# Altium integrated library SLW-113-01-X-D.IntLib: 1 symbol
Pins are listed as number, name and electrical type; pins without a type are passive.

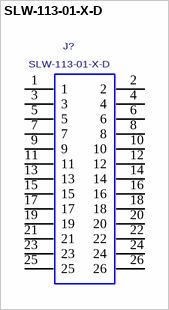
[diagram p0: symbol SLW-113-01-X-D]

## SLW-113-01-X-D
designator J?
LOW PROFILE, DOUBLE ROW, 0.100"SOCKET STRIP ASSEMBLY.; MANUFACTURER: SAMTEC
footprint SLW-113-01-X-D
pins: 1, 2, 3, 4, 5, 6, 7, 8, 9, 10, 11, 12, 13, 14, 15, 16, 17, 18, 19, 20, 21, 22, 23, 24, 25, 26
